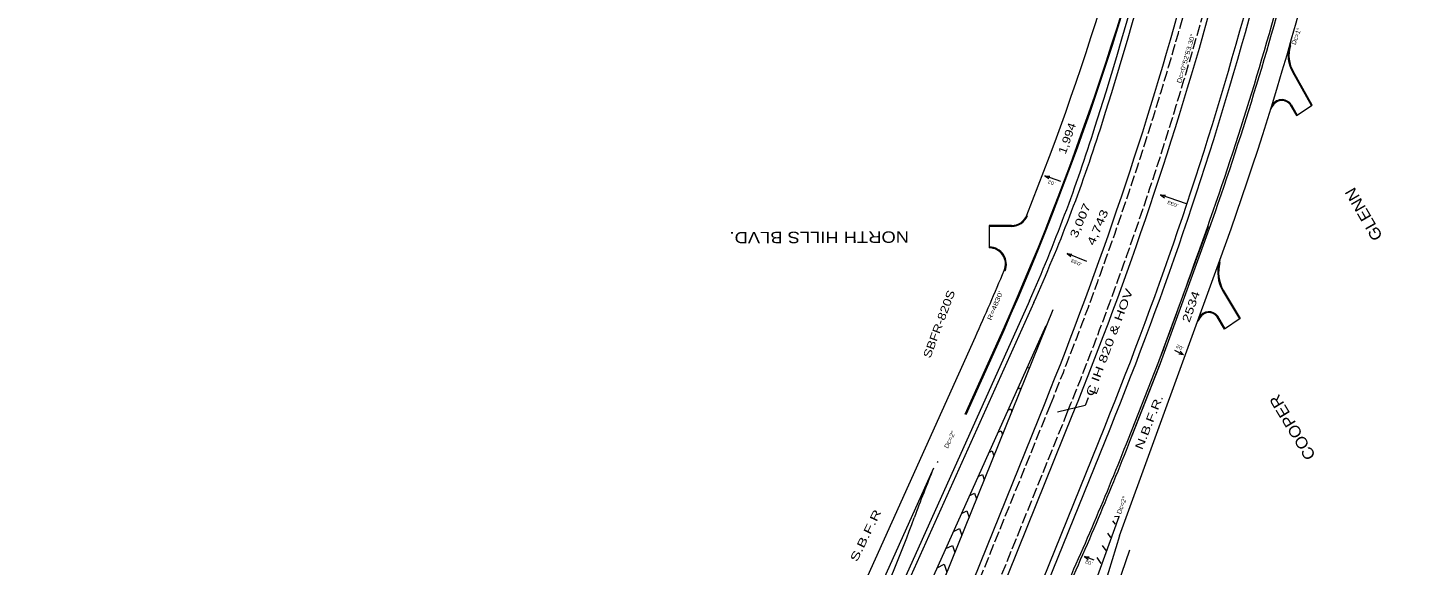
# Model space of a CAD drawing. Extents: x 2354993 to 2372084, y 6966390 to 6990057.
# Drawn here: x 2364099 to 2366527, y 6982315 to 6983254 of the extents above; entities that cross this region are included whole.
import ezdxf

# ---------------------------------------------------------------- set-up
doc = ezdxf.new("R2010")
doc.units = 0
doc.header["$LTSCALE"] = 3.2
doc.linetypes.add('LONG_DASHED', pattern=[7.5, 6, -1.5])
doc.linetypes.add('MEDIUM_DASHED', pattern=[4.5, 3, -1.5])
for name, color, linetype, lineweight in [('11', 7, 'Continuous', 13), ('13', 7, 'Continuous', 13), ('17', 7, 'Continuous', 13), ('19', 7, 'Continuous', 13), ('23', 7, 'Continuous', 13), ('25', 7, 'Continuous', 13), ('28', 7, 'Continuous', 13), ('4', 7, 'Continuous', 13), ('5', 7, 'Continuous', 13), ('7', 7, 'Continuous', 13), ('9', 7, 'Continuous', 13)]:
    doc.layers.add(name, color=color, linetype=linetype, lineweight=lineweight)

msp = doc.modelspace()

# ---------------------------------------------------------------- linework, layer by layer
at = {"layer": '11'}
for q in [(2366104.775, 6982690.097), (2366111.771, 6982683.473), (2366114.173, 6982688.989)]:
    msp.add_line((2366119.96, 6982682.603), q, dxfattribs=at)
at = {"layer": '13'}
msp.add_lwpolyline([(2365953.55, 6982607.162), (2365948.22, 6982593.653), (2365899.746, 6982582.544)], dxfattribs=at)
at = {"layer": '19'}
for p, q in [((2365877.738, 6982995.496), (2365884.513, 6982990.691)), ((2365877.738, 6982995.496), (2365886.033, 6982994.982)), ((2365905.646, 6982985.641), (2365877.738, 6982995.496)), ((2366080.067, 6982961.981), (2366088.367, 6982961.561)), ((2365916.553, 6982859.644), (2365924.81, 6982858.713)), ((2365946.856, 6982329.752), (2365953.6, 6982324.903)), ((2365946.856, 6982329.752), (2365955.148, 6982329.183)), ((2365963.796, 6982323.645), (2365946.856, 6982329.752))]:
    msp.add_line(p, q, dxfattribs=at)
for points in [[(2366125.148, 6982946.648), (2366080.067, 6982961.981), (2366086.9, 6982957.253)], [(2365950.852, 6982845.561), (2365916.553, 6982859.644), (2365923.08, 6982854.503)]]:
    msp.add_lwpolyline(points, dxfattribs=at)
at = {"layer": '23'}
msp.add_arc((2359111.542, 6985307.18), 7447.48, 339.24494, 340.82945, dxfattribs=at)
at = {"layer": '25'}
for p, q in [((2366306.976, 6983222.524), (2366307.445, 6983227.753)), ((2366343.871, 6983118.358), (2366311.105, 6983176.578)), ((2366345.178, 6983119.094), (2366312.412, 6983177.314)), ((2366275.193, 6983116.514), (2366272.759, 6983112.093)), ((2366306.809, 6983119.535), (2366317.409, 6983100.667)), ((2366308.116, 6983120.27), (2366318.717, 6983101.402)), ((2366317.409, 6983100.667), (2366345.178, 6983119.094)), ((2365819.459, 6982908.623), (2365780.234, 6982908.603)), ((2365780.234, 6982908.603), (2365780.254, 6982869.535)), ((2365819.46, 6982907.123), (2365780.235, 6982907.103)), ((2366183.786, 6982843.837), (2366184.444, 6982849.724)), ((2366189.372, 6982795.538), (2366219.038, 6982746.109)), ((2365858.107, 6982773.741), (2365517.469, 6982017.581)), ((2366188.086, 6982794.766), (2366217.752, 6982745.337)), ((2365655.565, 6982177.229), (2365892.178, 6982761.724)), ((2366148.809, 6982746.989), (2366144.9, 6982741.33)), ((2366191.891, 6982727.318), (2366178.711, 6982749.116)), ((2366193.174, 6982728.094), (2366179.994, 6982749.892)), ((2365879.26, 6982733.049), (2365636.764, 6982194.747)), ((2366219.038, 6982746.109), (2366191.891, 6982727.318)), ((2365506.33, 6982159.631), (2365756.042, 6982713.951)), ((2365738.464, 6982578.76), (2365792.056, 6982697.727)), ((2365739.895, 6982578.274), (2365793.424, 6982697.111)), ((2366030.231, 6982541.336), (2366077.003, 6982660.345)), ((2365700.058, 6982159.218), (2365878.037, 6982598.874)), ((2365748.722, 6982139.518), (2365926.701, 6982579.174)), ((2365682.891, 6982484.607), (2365682.892, 6982484.609))]:
    msp.add_line(p, q, dxfattribs=at)
at = {"layer": '25', "linetype": 'LONG_DASHED'}
for p, q in [((2365709.327, 6982155.466), (2365887.306, 6982595.122)), ((2365739.453, 6982143.27), (2365917.432, 6982582.926))]:
    msp.add_line(p, q, dxfattribs=at)
at = {"layer": '25', "linetype": 'MEDIUM_DASHED'}
msp.add_line((2365688.987, 6982495.873), (2365691.036, 6982494.939), dxfattribs=at)
at = {"layer": '25'}
msp.add_lwpolyline([(2365682.892, 6982484.609), (2365562.57, 6982217.518), (2365573.511, 6982212.589)], dxfattribs=at)
for centre, radius, start, end in [((2361244.215, 6984746.454), 4988, 335.74923, 358.78496), ((2361244.215, 6984746.454), 4989.5, 335.74923, 358.78496), ((2361361.727, 6984722.767), 4830.559, 338.17176, 359.03629), ((2359877.328, 6985028.058), 6473.75, 337.9611, 351.54233), ((2359877.328, 6985028.057), 6526.25, 337.9611, 351.54396), ((2359877.328, 6985028.057), 6586.25, 337.9611, 351.54396), ((2359877.328, 6985028.057), 6596.25, 337.9611, 351.54396), ((2366359.464, 6983205.904), 56.557, 162.42922, 211.23262), ((2366359.464, 6983205.904), 55.057, 162.42922, 211.23262), ((2366291.881, 6983108.766), 19.898, 35.31996, 155.09404), ((2366291.881, 6983108.766), 18.398, 35.31996, 155.09404), ((2363246.117, 6983950.399), 2864.789, 335.74921, 342.26078), ((2365819.445, 6982937.123), 28.5, 270.02906, 338.42308), ((2365819.445, 6982937.123), 30, 270.02906, 338.42308), ((2365780.269, 6982841.035), 30, 337.21464, 90.02906), ((2365780.269, 6982841.035), 28.5, 337.21464, 90.02993), ((2366247.261, 6982826.707), 67.246, 164.89773, 208.35832), ((2366247.261, 6982826.707), 65.746, 164.89773, 208.35832), ((2361116.677, 6984801.972), 5087.587, 335.7691, 337.19444), ((2366164.42, 6982738.739), 19.156, 35.60713, 152.14429), ((2366164.42, 6982738.739), 17.656, 35.60713, 152.14429), ((2368349.917, 6981400.909), 2878.789, 157.88653, 159.73969), ((2362974.286, 6983383.498), 2850.789, 335.74918, 339.77145)]:
    msp.add_arc(centre, radius, start, end, dxfattribs=at)
at = {"layer": '25', "linetype": 'LONG_DASHED'}
for centre, radius, end in [((2359877.328, 6985028.058), 6483.75, 346.60187), ((2359877.328, 6985028.057), 6516.25, 346.60718)]:
    msp.add_arc(centre, radius, 337.9611, end, dxfattribs=at)
at = {"layer": '25'}
msp.add_ellipse((2359801.786, 6985036.219), major_axis=(6478.123, 0), ratio=0.996776, start_param=5.97499933, end_param=6.13557103, dxfattribs=at)
at = {"layer": '4'}
for p, q in [((2366073.227, 6982661.608), (2366163.84, 6982907.068)), ((2365850.813, 6982777.027), (2365510.175, 6982020.867))]:
    msp.add_line(p, q, dxfattribs=at)
for points in [[(2365846.661, 6982659.924), (2365849.126, 6982661.129), (2365850.154, 6982658.083)], [(2365830.083, 6982623.123), (2365833.69, 6982624.887), (2365835.097, 6982620.721)], [(2365813.367, 6982586.017), (2365818.081, 6982588.322), (2365819.854, 6982583.069)], [(2365795.928, 6982547.304), (2365800.887, 6982549.729), (2365803.375, 6982542.36)], [(2365779.892, 6982511.707), (2365785.684, 6982514.539), (2365788.607, 6982505.88)], [(2365760.91, 6982469.57), (2365768.52, 6982473.291), (2365771.655, 6982464.004)], [(2365746.098, 6982436.69), (2365754.652, 6982440.872), (2365758.126, 6982430.583)], [(2365731.898, 6982405.168), (2365741.237, 6982409.734), (2365745.079, 6982398.354)], [(2365717.673, 6982373.591), (2365728.082, 6982378.68), (2365732.189, 6982366.514)], [(2365704.204, 6982343.692), (2365715.987, 6982349.453), (2365720.214, 6982336.932)], [(2365689.17, 6982310.318), (2365701.705, 6982316.447), (2365706.351, 6982302.686)]]:
    msp.add_lwpolyline(points, dxfattribs=at)
for centre, radius, start, end in [((2359877.328, 6985028.058), 6391.75, 342.25932, 351.54233), ((2363191.065, 6983952.323), 2907.848, 336.16019, 342.55197)]:
    msp.add_arc(centre, radius, start, end, dxfattribs=at)
at = {"layer": '5'}
for p, q in [((2366163.734, 6982906.741), (2366163.736, 6982906.748)), ((2366008.225, 6982366.256), (2366183.609, 6982847.881)), ((2366077.494, 6982661.687), (2366149.782, 6982860.199)), ((2366023.798, 6982535.903), (2366075.709, 6982667.989)), ((2366027.521, 6982534.44), (2366079.432, 6982666.526)), ((2365804.338, 6982117.004), (2365982.317, 6982556.66)), ((2365813.607, 6982113.252), (2365991.586, 6982552.908)), ((2365895.848, 6982092.73), (2366007.685, 6982399.844)), ((2365996.066, 6982392.476), (2366000.581, 6982386.18)), ((2366008.194, 6982399.872), (2365999.64, 6982399.403)), ((2366008.225, 6982366.256), (2365938.683, 6982140.218)), ((2365987.02, 6982370.772), (2365992.292, 6982363.419)), ((2366025.609, 6982341.071), (2365866.293, 6981881.435)), ((2365977.842, 6982349.25), (2365984.004, 6982340.659)), ((2365968.536, 6982327.909), (2365975.715, 6982317.898))]:
    msp.add_line(p, q, dxfattribs=at)
for centre, radius, start, end in [((2360811.157, 6984804.27), 5717.578, 339.9908, 358.60851), ((2360811.157, 6984804.27), 5677.578, 339.99081, 344.99116), ((2360811.157, 6984804.27), 5681.578, 339.99081, 344.99116), ((2360717.318, 6984621.39), 5701.578, 335.3684, 338.5448), ((2360717.318, 6984621.39), 5705.578, 335.3684, 338.5448)]:
    msp.add_arc(centre, radius, start, end, dxfattribs=at)
at = {"layer": '9'}
msp.add_arc((2360722.521, 6984327.136), 5729.573, 359.50797, 359.50797, dxfattribs=at)

# ---------------------------------------------------------------- texts
at = {"layer": '13'}
for s, height, rotation, width, p in [('1,994', 14, 70.625, 1.2, (2365913.767, 6983032.14)), ('GLENN', 20, 119.996, 1.1, (2366469.209, 6982889.386)), ('3,007', 14, 66.892, 1.35, (2365933.429, 6982885.399)), ('4,743', 14, 67.145, 1.4, (2365963.549, 6982872.384)), ('NORTH HILLS BLVD.', 20, 180.22, 1.2, (2365639.926, 6982898.482)), ('C IH 820 & HOV ', 14, 69.296, 1.45, (2365961.818, 6982608.637)), ('SBFR-820S', 14, 69.451, 1.25, (2365677.243, 6982675.548)), ('2534', 14, 70.763, 1.35, (2366130.359, 6982737.81)), ('N.B.F.R.', 14, 68.262, 1.4, (2366047.734, 6982515.488)), ('COOPER', 20, 121.158, 1.1, (2366352.081, 6982506.215)), ('S.B.F.R', 14, 63.994, 1.5, (2365548.85, 6982319.471))]:
    msp.add_text(s, height=height, rotation=rotation, dxfattribs=dict(at, width=width)).set_placement(p)
at = {"layer": '17'}
for s, rotation, width, p in [("R=4830'", 67.249, 1.35, (2365783.775, 6982742.08)), ('Dc=2°', 64.778, 1.1, (2365708.14, 6982518.079))]:
    msp.add_text(s, height=8, rotation=rotation, dxfattribs=dict(at, width=width)).set_placement(p)
at = {"layer": '19'}
msp.add_text('Dc=1°', height=8, rotation=69.68, dxfattribs=at).set_placement((2366315.848, 6983223.82))
for s, height, rotation, width, p in [('.02', 6, 160.591, 1.25, (2365897.029, 6982983.671)), ('.033', 6, 158.267, 1.3, (2366111.984, 6982944.998)), ('.033', 6, 158.267, 1.3, (2365943.607, 6982842.629)), ('.02', 6, 154.917, 1.3, (2366121.767, 6982695.024)), ('Dc=2°', 8, 69.681, 1.1, (2366010.431, 6982403.229)), ('.02', 6, 160.217, 1.25, (2365962.252, 6982319.579))]:
    msp.add_text(s, height=height, rotation=rotation, dxfattribs=dict(at, width=width)).set_placement(p)
at = {"layer": '28', "width": 1.4}
msp.add_text('L ', height=14, rotation=69.296, dxfattribs=at).set_placement((2365967.564, 6982611.832))
at = {"layer": '7', "width": 1.2}
msp.add_text('Dc=0°52\'53.30"', height=8, rotation=73.593, dxfattribs=at).set_placement((2366115.556, 6983156.593))

doc.saveas('drawing.dxf')
